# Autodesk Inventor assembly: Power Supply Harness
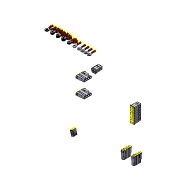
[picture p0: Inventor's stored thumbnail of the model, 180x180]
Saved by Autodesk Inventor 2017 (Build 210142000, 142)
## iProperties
Created: 2007-02
Part Number: Power Supply Harness
Document SubType Name: Assembly
Designer: DanielSeverino
Author: DanielSeverino
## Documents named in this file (6)
- C:\Users\DanielSeverino\Desktop\01\Power Supply Harness.iam
- C:\Users\DanielSeverino\Desktop\01\Power Supply Connector.ipt
- C:\Users\DanielSeverino\Desktop\01\Power Supply AUX Connector.ipt
- C:\Users\DanielSeverino\Desktop\01\Drive Power Connector.ipt
- C:\Users\DanielSeverino\Desktop\01\Floppy Drive Power Connector.ipt
- C:\Users\DanielSeverino\Desktop\01\Terminal Ring.ipt
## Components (39 placed, 5 different names)
1. Power Supply Connector:1
2. Power Supply AUX Connector:1
3. Drive Power Connector:1
4. Drive Power Connector:2
5. Floppy Drive Power Connector:1
6. Drive Power Connector:3
7. Drive Power Connector:4
8. Terminal Ring:1
9. Terminal Ring:2
10. Terminal Ring:3
11. Terminal Ring:4
12. Terminal Ring:5
13. Terminal Ring:6
14. Terminal Ring:7
15. Terminal Ring:8
16. Terminal Ring:9
17. Terminal Ring:10
18. Terminal Ring:11
19. Terminal Ring:12
20. Terminal Ring:13
21. Terminal Ring:14
22. Terminal Ring:15
23. Terminal Ring:16
24. Terminal Ring:17
25. Terminal Ring:18
26. Terminal Ring:19
27. Terminal Ring:20
28. Terminal Ring:21
29. Terminal Ring:22
30. Terminal Ring:23
31. Terminal Ring:24
32. Terminal Ring:25
33. Terminal Ring:26
34. Terminal Ring:27
35. Terminal Ring:28
36. Terminal Ring:29
37. Terminal Ring:30
38. Terminal Ring:31
39. Terminal Ring:32
